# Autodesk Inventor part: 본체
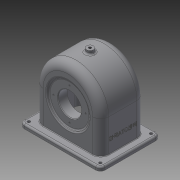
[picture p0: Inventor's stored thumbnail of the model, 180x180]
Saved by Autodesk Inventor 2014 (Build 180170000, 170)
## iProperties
Created: 2016-01
Part Number: 본체
Material: Generic
Document SubType Name: Modeling
Designer: user
Density: 1 g/cm^3
Appearance: Default
Author: user
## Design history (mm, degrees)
sketch "Sketch1"
  geometry: L1 (-57, -64)-(57, -64); L2 (-57, 0)-(-57, -64); L3 (57, 0)-(57, -64); A1 r 57 centre (0, 0) between (-57, 0) and (57, 0); 2 further points
  constraints: 6 end point, 2 perpendicular, 2 point on circle, 2 tangent, 1 centre point, 1 coincident, 1 horizontal, 1 midpoint, 1 vertical alignment
  dimensions: "d0" = 57 radius of A1; "d1" = 64 distance from line of L1 A1.centre
extrude "Extrusion1" new body sketch "Sketch1" stored distance "d2" = 77; taper "d3" = 0 deg
sketch "Sketch12"
  geometry: L1 (-57, -64)-(-57, 0) reference; L2 (57, 0)-(57, -64) reference; L3 (-51, -64)-(-51, 0); L4 (51, 0)-(51, -64); L5 (57, -64)-(-57, -64) reference; L6 (-51, -64)-(51, -64); A1 r 57 centre (0, 0) between (57, 0) and (-57, 0) reference; A2 r 51 centre (0, 0) between (51, 0) and (-51, 0); 1 further point
  constraints: 6 end point, 2 point on circle, 1 centre point, 1 collinear, 2 other
  dimensions: "d101" = 6 radial gap between concentric circles of A1 A2; "d102" = 64 distance from line of point (0, 0) L6
extrude "Extrusion5" cut sketch "Sketch12" stored distance "d103" = 67; taper "d104" = 0 deg
sketch "Sketch13"
  geometry: L1 (-4, 55.562)-(-4, -74.613); L2 (-64, -33.5)-(-64, 33.5) reference; L3 (-4, -48.5)-(27, -48.5); L4 (0, -33.5)-(51, -33.5) reference; L5 (27, -48.5)-(27, -38.5); L6 (27, -38.5)-(-4, -38.5); L7 (0, -38.5)-(57, -38.5) reference; L8 (-4, 19.5)-(24, 19.5); L9 (0, 33.5)-(0, -33.5) reference; L10 (24, 19.5)-(35.747, 33.5); L11 (33.416, 38.5)-(30.899, 35.5); L12 (30.899, 35.5)-(-4, 35.5); L13 (57, 38.5)-(0, 38.5) reference; L14 (51, 33.5)-(0, 33.5) reference; L15 (35.747, 33.5)-(33.416, 38.5); L16 (33.416, 38.5)-(-4, 38.5); L17 (0, 38.5)-(-64, 38.5) reference; 1 further point
  constraints: 20 end point, 9 point on line, 4 perpendicular, 2 parallel, 1 vertical
  dimensions: "d105" = 60 distance between parallel lines of L1 L2; "d106" = 10 distance of L3.end L5.end; "d107" = 62 diameter of L5 L1; "d108" = 3 distance between parallel lines of L13 L12; "d109" = 56 diameter of L8.end L1; "d110" = 50 deg angle of L8 L10; "d111" = 5 distance between parallel lines of L10 L11; "d112" = 16 distance between parallel lines of L8 L12
revolve "Revolution3" stored, may be unused: angle "d113" = 90 deg
revolve "Revolution4" stored, may be unused: angle "d114" = 90 deg
hole "Hole6" diameter "d117" = 40; stored, may be unused: countersink angle "d121" = 90 deg, drill point angle "d123" = 118 deg; dims "d115" = 10, "d116" = 10, "d118" = 7, "d119" = 4, "d120" = 2, "d122" = 9
sketch "Sketch14" dims "d124" = 48
  geometry: C1 r 37.416 at (0, 0) reference; 3 further points
  constraints: 2 vertical alignment, 1 coincident, 2 other
hole "Hole7" sketch "Sketch14" at (0, 24) diameter "d125" = 2.459; stored, may be unused: countersink angle "d129" = 90 deg, drill point angle "d131" = 118 deg; dims "d126" = 6, "d127" = 4, "d128" = 2, "d130" = 8
sketch "Sketch15" dims "d132" = 56
  geometry: C1 r 20 at (0, 0) reference; C2 r 34.899 at (0, 0) reference; 3 further points
  constraints: 2 vertical alignment, 1 coincident, 2 other
hole "Hole8" sketch "Sketch15" at (0, 28) diameter "d133" = 2.459; stored, may be unused: countersink angle "d137" = 90 deg, drill point angle "d139" = 118 deg; dims "d134" = 7, "d135" = 4, "d136" = 2, "d138" = 9
pattern_circular "Circular Pattern3" dims angle "d141" = 360 deg
sketch "Sketch16"
  geometry: L1 (114, -77)-(114, 0) reference; L2 (0, 0)-(114, 0) reference; L3 (0, 0)-(0, -77) reference; L4 (114, -77)-(0, -77) reference; L5 (-5, 13.5)-(119, 13.5); L6 (127, 5.5)-(127, -82.5); L7 (119, -90.5)-(-5, -90.5); L8 (-13, -82.5)-(-13, 5.5); L9 (-13, 13.5)-(127, -90.5); L10 (127, 13.5)-(-13, -90.5); C1 r 2.5 at (-5, 5.5); C2 r 2.5 at (-5, -82.5); C3 r 2.5 at (119, -82.5); C4 r 2.5 at (119, 5.5); A1 r 8 centre (-5, 5.5) between (-5, 13.5) and (-13, 5.5); A2 r 8 centre (-5, -82.5) between (-13, -82.5) and (-5, -90.5); A3 r 8 centre (119, -82.5) between (119, -90.5) and (127, -82.5); A4 r 8 centre (119, 5.5) between (127, 5.5) and (119, 13.5); 1 further point
  constraints: 12 end point, 8 centre point, 8 point on circle, 8 point on line, 8 tangent, 4 coincident, 3 equal radius, 2 midpoint, 2 parallel, 1 horizontal, 1 perpendicular
  dimensions: "d143" = 140 distance of L9.start L10.start; "d144" = 104 distance of L10.end L9.start; "d145" = 8 radius of A1; "d146" = 5 diameter of C1; "d147" = 5 diameter of C2; "d148" = 5 diameter of C3; "d149" = 5 diameter of C4
extrude "Extrusion6" join sketch "Sketch16" distance "d150" = 7; taper "d151" = 0 deg
workplane "Work Plane2"
sketch "Sketch18"
  geometry: C1 r 6 at (62, 52); 1 further point
  constraints: 1 centre point, 1 coincident
  dimensions: "d154" = 12 diameter of C1
extrude "Extrusion7" join sketch "Sketch18" stored distance "d155" = 7; taper "d156" = 0 deg
hole "Hole9" diameter "d159" = 4.459; stored, may be unused: countersink angle "d163" = 90 deg, drill point angle "d165" = 118 deg; dims "d157" = 10, "d158" = 10, "d160" = 7, "d161" = 4, "d162" = 2, "d164" = 9
fillet "Fillet3" dims "d166" = 9, "d167" = 14, "d168" = 1, "d169" = 3
chamfer "Chamfer3" distance "d170" = 1; stored, may be unused: second distance "d171" = 2, angle "d172" = 45 deg
chamfer "Chamfer4" distance "d173" = 1; stored, may be unused: second distance "d174" = 2, angle "d175" = 45 deg
sketch "Sketch19"
  geometry: L1 (0, 56)-(-49, 56) reference; L2 (-49.387, 25.602)-(0.387, 25.602); L3 (0.387, 25.602)-(0.387, 18.398); L4 (0.387, 18.398)-(-49.387, 18.398); L5 (-49.387, 18.398)-(-49.387, 25.602); L6 (19.5, -8)-(-68.5, -8) reference; 4 further points
  constraints: 3 midpoint, 1 vertical alignment, 2 other
  dimensions: "d176" = 30 distance from line of L6 point (-49.387, 22)
emboss "Emboss2" sketch "Sketch19" dims "d177" = 0.5, "d178" = 0
sketch "Sketch17"
  geometry: C1 r 6 at (62, 52); 1 further point
  constraints: 1 centre point, 1 coincident
  dimensions: "d153" = 12 diameter of C1
sketch "Sketch3"
  geometry: L1 (108, -73)-(6, -73) reference; L2 (6, -73)-(6, -6) reference; L3 (6, -6)-(108, -6) reference; L4 (108, -6)-(108, -73) reference; L5 (-5, 13.5)-(119, 13.5); L6 (127, 5.5)-(127, -82.5); L7 (119, -90.5)-(-5, -90.5); L8 (-13, -82.5)-(-13, 5.5); L9 (-13, 13.5)-(127, -90.5); L10 (127, 13.5)-(-13, -90.5); A1 r 8 centre (-5, 5.5) between (-5, 13.5) and (-13, 5.5); A2 r 8 centre (-5, -82.5) between (-13, -82.5) and (-5, -90.5); A3 r 8 centre (119, -82.5) between (119, -90.5) and (127, -82.5); A4 r 8 centre (119, 5.5) between (127, 5.5) and (119, 13.5); 1 further point
  constraints: 12 end point, 8 point on circle, 8 point on line, 8 tangent, 4 centre point, 3 equal radius, 2 midpoint, 2 parallel, 1 horizontal, 1 perpendicular
  dimensions: "d5" = 140 distance of L9.start L10.start; "d6" = 104 distance of L10.start L9.end; "d7" = 8 radius of A1
extrude "Extrusion2" join sketch "Sketch3" distance "d8" = 7; taper "d9" = 0 deg
sketch "Sketch6"
  geometry: L1 (-3.5, 74.308)-(-3.5, -74.614); L2 (-64, -44)-(-64, -52) reference; L3 (-64, -39.5)-(-64, -33.5) reference; L4 (51, 33.5)-(0, 33.5) reference; L5 (21.5, 14.5)-(37.443, 33.5); L6 (-3.5, -53.5)-(27.5, -53.5); L7 (27.5, -53.5)-(27.5, -33.5); L8 (-3.5, -33.5)-(27.5, -33.5); L9 (63, 2.229)-(63, -2.23) reference; L10 (51, -33.5)-(51, 33.5) reference; L11 (28.399, 30.5)-(-3.5, 30.5); L12 (21.5, 14.5)-(-3.5, 14.5); L13 (28.399, 30.5)-(30.916, 33.5); L14 (30.916, 33.5)-(-3.5, 33.5); L15 (30.916, 33.5)-(37.443, 33.5); 7 further points; 3 other entities
  constraints: 20 end point, 6 point on line, 3 perpendicular, 1 horizontal, 1 parallel, 1 vertical, 6 other
  dimensions: "d23" = 60.5 distance between parallel lines of L1 L2; "d26" = 87 dimension on L6; "d27" = 62 diameter of L7 L1; "d34" = 3 dimension on L11; "d35" = 50 deg angle of L12 L5; "d36" = 5 distance between parallel lines of L5 L13; "d37" = 16 distance between parallel lines of L12 L11; "d38" = 50 diameter of L5.start L1
revolve "Revolution1" stored, may be unused: angle "d39" = 90 deg
revolve "Revolution2" stored, may be unused: angle "d40" = 90 deg
hole "Hole2" diameter "d43" = 40; stored, may be unused: countersink angle "d47" = 90 deg, drill point angle "d49" = 0 deg; dims "d44" = 6, "d45" = 4, "d46" = 2, "d48" = 16, "d50" = 10, "d51" = 10
sketch "Sketch7" dims "d52" = 48
  geometry: C1 r 31 at (0, 0) reference; 3 further points
  constraints: 2 vertical alignment, 1 coincident, 2 other
hole "Hole3" sketch "Sketch7" at (0, 24) diameter "d53" = 2.459; stored, may be unused: countersink angle "d57" = 90 deg, drill point angle "d59" = 118 deg; dims "d54" = 6, "d55" = 4, "d56" = 2, "d58" = 8
pattern_circular "Circular Pattern1" dims angle "d61" = 360 deg
sketch "Sketch8" dims "d63" = 56
  geometry: C1 r 31.899 at (0, 0) reference; 3 further points
  constraints: 2 vertical alignment, 1 coincident, 2 other
hole "Hole4" sketch "Sketch8" at (0, 28) diameter "d64" = 2.459; stored, may be unused: countersink angle "d68" = 90 deg, drill point angle "d70" = 118 deg; dims "d65" = 7, "d66" = 4, "d67" = 2, "d69" = 9
pattern_circular "Circular Pattern2" dims angle "d72" = 360 deg
sketch "Sketch9"
  geometry: A1 r 8 centre (-11, -10.5) between (-19, -10.5) and (-11, -18.5) reference; A2 r 8 centre (113, -10.5) between (113, -18.5) and (121, -10.5) reference; A3 r 8 centre (113, 77.5) between (121, 77.5) and (113, 85.5) reference; A4 r 8 centre (-11, 77.5) between (-11, 85.5) and (-19, 77.5) reference; 1 further point
hole "Hole5" sketch "Sketch9" at (-11, -10.5), (113, -10.5), (113, 77.5), (-11, 77.5) diameter "d74" = 5; stored, may be unused: countersink angle "d78" = 90 deg, drill point angle "d80" = 118 deg; dims "d75" = 7, "d76" = 4, "d77" = 2, "d79" = 9
chamfer "Chamfer1" distance "d86" = 1; stored, may be unused: second distance "d87" = 2, angle "d88" = 45 deg
chamfer "Chamfer2" distance "d89" = 1; stored, may be unused: second distance "d90" = 2, angle "d91" = 45 deg
body "Solid1"
other parameters: "d152" = -127
